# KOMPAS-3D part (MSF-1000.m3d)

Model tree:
1. Ось X
2. Ось Y
3. Ось Z
4. Начало координат  (labels: Операция без истории:1)

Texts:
  Линия-выноска #1
  Линия-выноска #2
  Линия-выноска #3
  Отклонения формы и база
  Марка координационной оси
  Марка/позиционное обозначение с линией-выноской
  Марка/позиционное обозначение на линии
  Марка/позиционное обозначение без линии-выноски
